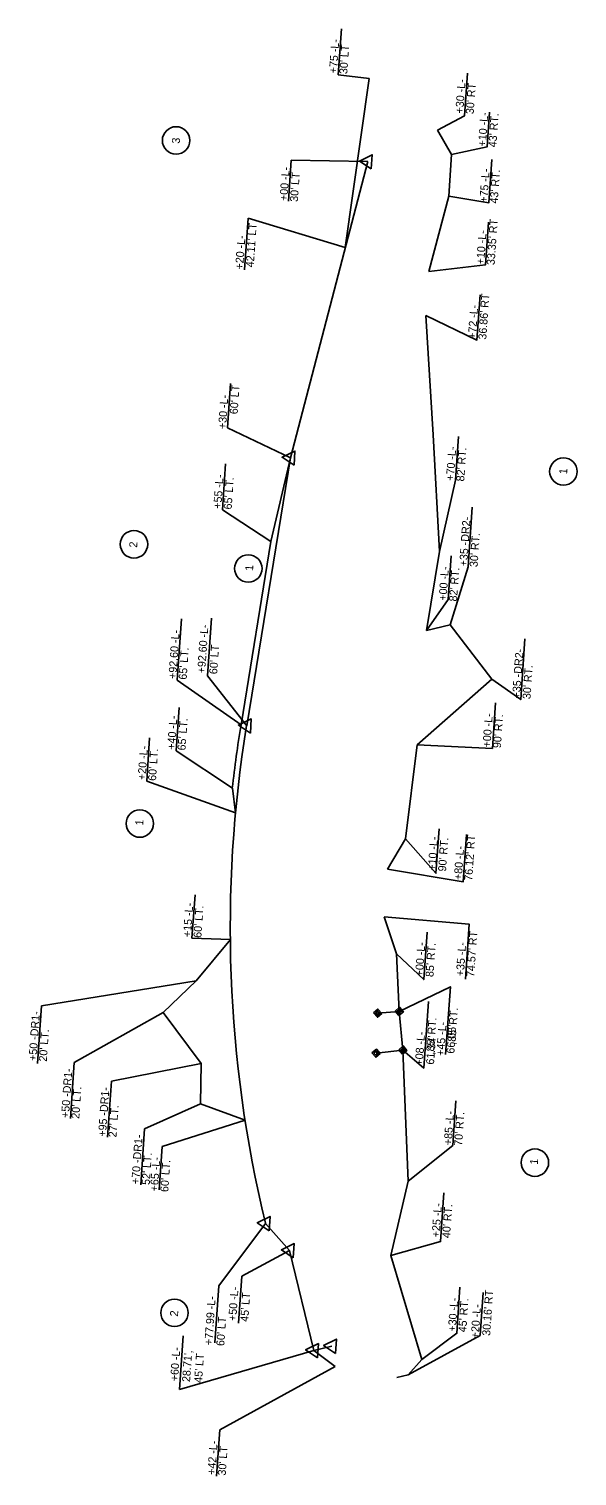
# Model space of a CAD drawing. Extents: x 2599205 to 2599684, y 728753 to 730019.
import ezdxf

# ---------------------------------------------------------------- set-up
doc = ezdxf.new("R2010")
doc.units = 0
for name, color, linetype in [('Default', 7, 'Continuous'), ('Prop Easement Construction', 7, 'Continuous'), ('Prop Easement Construction Station Offsets', 7, 'Continuous'), ('Prop Easement Permanent Drainage', 7, 'Continuous'), ('Prop Easement Permanent Drainage Station Offsets', 7, 'Continuous'), ('Prop Parcel Number CELL', 7, 'Continuous'), ('Prop ROW Marker CELL', 7, 'Continuous'), ('Prop ROW Permanent Easement CELL', 7, 'Continuous'), ('Prop ROW RW Lines', 7, 'Continuous'), ('Prop ROW Station Offsets', 7, 'Continuous')]:
    doc.layers.add(name, color=color, linetype=linetype)

msp = doc.modelspace()

# ---------------------------------------------------------------- linework, layer by layer
at = {"layer": 'Default'}
msp.add_line((2599526.3, 728839.4), (2599536.2, 728841.8), dxfattribs=at)
at = {"layer": 'Prop Easement Construction'}
for p, q in [((2599481.2, 729827.7), (2599502.2, 729975.7)), ((2599574.3, 729909.3), (2599562.1, 729930.5)), ((2599571.9, 729872.8), (2599574.3, 729909.3)), ((2599554.4, 729806.8), (2599571.9, 729872.8)), ((2599558.2, 729664), (2599551.8, 729768.4)), ((2599563.8, 729561.8), (2599558.2, 729664)), ((2599416.3, 729570.6), (2599433.3, 729643.9)), ((2599390.2, 729410.4), (2599416.3, 729570.6)), ((2599552.5, 729492.7), (2599563.8, 729561.8)), ((2599552.5, 729492.7), (2599573, 729497.9)), ((2599609.5, 729450.3), (2599573, 729497.9)), ((2599544.3, 729392.7), (2599609.5, 729450.3)), ((2599534, 729310.5), (2599544.3, 729392.7)), ((2599385.4, 729333.4), (2599382.6, 729355)), ((2599518.2, 729283.9), (2599534, 729310.5)), ((2599526, 729210), (2599515.4, 729242.3)), ((2599350.8, 729186.3), (2599380.8, 729222.5)), ((2599528.5, 729159.6), (2599526, 729210)), ((2599322.1, 729158.5), (2599350.8, 729186.3)), ((2599355.3, 729114.1), (2599322.1, 729158.5)), ((2599536.3, 729011.1), (2599531.7, 729125.8)), ((2599354.7, 729078.8), (2599355.3, 729114.1)), ((2599393.6, 729064.5), (2599354.7, 729078.8)), ((2599521.1, 728946.2), (2599536.3, 729011.1)), ((2599548.3, 728855), (2599521.1, 728946.2)), ((2599472.6, 728849.1), (2599453.8, 728863.1)), ((2599536.2, 728841.8), (2599548.3, 728855))]:
    msp.add_line(p, q, dxfattribs=at)
msp.add_arc((2600480.7, 729232.5), 1105, 170.7363, 173.6343, dxfattribs=at)
at = {"layer": 'Prop Easement Construction Station Offsets'}
for p, q in [((2599475.2, 729978.8), (2599478, 730019)), ((2599502.2, 729975.7), (2599475.2, 729978.8)), ((2599393.3, 729808.4), (2599396.4, 729853.4)), ((2599481.2, 729827.7), (2599396.4, 729853.4)), ((2599373.8, 729598.4), (2599376.5, 729638.6)), ((2599416.3, 729570.6), (2599373.8, 729598.4)), ((2599334.4, 729449.5), (2599338.1, 729503.1)), ((2599390.2, 729410.4), (2599334.4, 729449.5)), ((2599333.4, 729387.6), (2599336, 729425.4)), ((2599307.6, 729361.1), (2599310.2, 729398.9)), ((2599382.6, 729355), (2599333.4, 729387.6)), ((2599385.4, 729333.4), (2599307.6, 729361.1)), ((2599347.2, 729223.7), (2599349.9, 729261.5)), ((2599380.8, 729222.5), (2599347.2, 729223.7)), ((2599350.8, 729186.3), (2599215.5, 729164.5)), ((2599212, 729113.9), (2599215.5, 729164.5)), ((2599322.1, 729158.5), (2599244.3, 729114.9)), ((2599240.9, 729065.9), (2599244.3, 729114.9)), ((2599355.3, 729114.1), (2599276.7, 729098.5)), ((2599273.4, 729049.5), (2599276.7, 729098.5)), ((2599354.7, 729078.8), (2599305.8, 729057)), ((2599393.6, 729064.5), (2599321.2, 729041.4)), ((2599302.4, 729008), (2599305.8, 729057)), ((2599318.6, 729003.6), (2599321.2, 729041.4)), ((2599472.6, 728849.1), (2599371.6, 728793.5)), ((2599368.8, 728753.1), (2599371.6, 728793.5))]:
    msp.add_line(p, q, dxfattribs=at)
for points in [[(2599562.1, 729930.5), (2599585.6, 729942.9), (2599588.2, 729980.4)], [(2599574.3, 729909.3), (2599605.3, 729915.8), (2599607.4, 729946.3)], [(2599571.9, 729872.8), (2599607, 729867), (2599609.6, 729904.7)], [(2599554.4, 729806.8), (2599604.1, 729812.8), (2599606.6, 729850)], [(2599551.8, 729768.4), (2599596.5, 729746.8), (2599599.2, 729786.5)], [(2599563.8, 729561.8), (2599577.8, 729624.4), (2599580.4, 729662.5)], [(2599573, 729497.9), (2599588.8, 729548.6), (2599592.3, 729600.7)], [(2599552.5, 729492.7), (2599571.2, 729520), (2599573.8, 729558.1)], [(2599609.5, 729450.3), (2599634.8, 729432.3), (2599638.5, 729485.5)], [(2599544.3, 729392.7), (2599610, 729389.6), (2599612.7, 729429.5)], [(2599534, 729310.5), (2599560.6, 729280.5), (2599563.3, 729319.3)], [(2599518.2, 729283.9), (2599584.4, 729272.9), (2599587.3, 729314.3)], [(2599515.4, 729242.3), (2599589.8, 729235.8), (2599586.4, 729187.9)], [(2599526, 729210), (2599550, 729187.4), (2599552.9, 729228.9)], [(2599536.3, 729011.1), (2599575.4, 729042.4), (2599578.1, 729081.5)], [(2599521.1, 728946.2), (2599564.7, 728958.2), (2599567.6, 729000.8)], [(2599536.2, 728841.8), (2599599.3, 728876.2), (2599601.9, 728913.7)], [(2599548.3, 728855), (2599578.9, 728878.1), (2599581.6, 728918.5)]]:
    msp.add_lwpolyline(points, dxfattribs=at)
at = {"layer": 'Prop Easement Permanent Drainage'}
for p, q in [((2599528.5, 729159.6), (2599509.6, 729158.1)), ((2599531.7, 729125.8), (2599528.5, 729159.6)), ((2599508.2, 729123.1), (2599531.7, 729125.8))]:
    msp.add_line(p, q, dxfattribs=at)
at = {"layer": 'Prop Easement Permanent Drainage Station Offsets'}
for points in [[(2599528.5, 729159.6), (2599573.3, 729181.2), (2599569.1, 729121.9)], [(2599531.7, 729125.8), (2599550, 729110), (2599554, 729168.2)]]:
    msp.add_lwpolyline(points, dxfattribs=at)
at = {"layer": 'Prop Parcel Number CELL'}
for p, q in [((2599333.3, 729921.5), (2599333.3, 729921.5)), ((2599672.1, 729631.9), (2599672.1, 729631.9)), ((2599296.5, 729568.2), (2599296.5, 729568.2)), ((2599396.5, 729547), (2599396.5, 729547)), ((2599301.6, 729323.9), (2599301.6, 729323.9)), ((2599647.2, 729027.3), (2599647.2, 729027.3)), ((2599331.9, 728895.9), (2599331.9, 728895.9))]:
    msp.add_line(p, q, dxfattribs=at)
for centre in [(2599333.3, 729921.5), (2599672.1, 729631.9), (2599296.5, 729568.2), (2599396.5, 729547), (2599301.6, 729323.9), (2599647.2, 729027.3), (2599331.9, 728895.9)]:
    msp.add_circle(centre, 12, dxfattribs=at)
at = {"layer": 'Prop ROW Marker CELL'}
for p, q in [((2599500.9, 729903), (2599500.9, 729903)), ((2599433.3, 729643.9), (2599433.3, 729643.9)), ((2599395.1, 729409.5), (2599395.1, 729409.5)), ((2599509.6, 729158.1), (2599509.6, 729158.1)), ((2599528.5, 729159.6), (2599528.5, 729159.6)), ((2599508.2, 729123.1), (2599508.2, 729123.1)), ((2599531.7, 729125.8), (2599531.7, 729125.8)), ((2599411.5, 728974.2), (2599411.5, 728974.2)), ((2599432.6, 728950.5), (2599432.6, 728950.5)), ((2599453.8, 728863.1), (2599453.8, 728863.1)), ((2599469.6, 728866.9), (2599469.6, 728866.9))]:
    msp.add_line(p, q, dxfattribs=at)
for points in [[(2599504, 729896.6), (2599493.7, 729903.5), (2599504.9, 729909)], [(2599436.5, 729637.4), (2599426.1, 729644.3), (2599437.3, 729649.8)], [(2599398.3, 729403.1), (2599387.9, 729410), (2599399.1, 729415.5)], [(2599414.6, 728967.7), (2599404.3, 728974.7), (2599415.5, 728980.2)], [(2599435.8, 728944.1), (2599425.5, 728951), (2599436.7, 728956.5)], [(2599456.9, 728856.6), (2599446.6, 728863.5), (2599457.8, 728869)], [(2599472.8, 728860.4), (2599462.4, 728867.4), (2599473.6, 728872.9)]]:
    msp.add_lwpolyline(points, close=True, dxfattribs=at)
at = {"layer": 'Prop ROW Permanent Easement CELL'}
for points in [[(2599506, 729158.4), (2599509.9, 729161.7), (2599513.2, 729157.9), (2599509.4, 729154.5)], [(2599507.8, 729158.3), (2599509.8, 729159.9), (2599511.4, 729158), (2599509.5, 729156.3)], [(2599524.9, 729159.8), (2599528.8, 729163.2), (2599532.1, 729159.3), (2599528.3, 729156)], [(2599526.7, 729159.7), (2599528.7, 729161.4), (2599530.3, 729159.5), (2599528.4, 729157.8)], [(2599528.1, 729126), (2599532, 729129.4), (2599535.3, 729125.5), (2599531.5, 729122.2)], [(2599529.9, 729125.9), (2599531.8, 729127.6), (2599533.5, 729125.6), (2599531.6, 729124)], [(2599504.6, 729123.4), (2599508.5, 729126.7), (2599511.8, 729122.9), (2599508, 729119.5)], [(2599506.4, 729123.2), (2599508.3, 729124.9), (2599510, 729123), (2599508.1, 729121.3)]]:
    msp.add_lwpolyline(points, close=True, dxfattribs=at)
at = {"layer": 'Prop ROW RW Lines'}
for p, q in [((2599433.3, 729643.9), (2599500.9, 729903)), ((2599395.1, 729409.5), (2599433.3, 729643.9)), ((2599432.6, 728950.5), (2599411.5, 728974.2)), ((2599453.8, 728863.1), (2599432.6, 728950.5)), ((2599469.6, 728866.9), (2599453.8, 728863.1))]:
    msp.add_line(p, q, dxfattribs=at)
msp.add_arc((2600480.7, 729232.5), 1100, 170.7363, 193.5781, dxfattribs=at)
at = {"layer": 'Prop ROW Station Offsets'}
for p, q in [((2599434.1, 729904.3), (2599431.6, 729868.4)), ((2599500.9, 729903), (2599434.1, 729904.3)), ((2599380.9, 729708.8), (2599378.2, 729670.2)), ((2599433.3, 729643.9), (2599378.2, 729670.2)), ((2599364.3, 729503.6), (2599360.8, 729453.1)), ((2599395.1, 729409.5), (2599360.8, 729453.1)), ((2599411.5, 728974.2), (2599370.6, 728919.4)), ((2599432.6, 728950.5), (2599390.7, 728928.1)), ((2599387.8, 728887), (2599390.7, 728928.1)), ((2599370.6, 728919.4), (2599367.1, 728869.6)), ((2599336.3, 728828.9), (2599339.6, 728875.9)), ((2599453.8, 728863.1), (2599336.3, 728828.9))]:
    msp.add_line(p, q, dxfattribs=at)

# ---------------------------------------------------------------- texts
at = {"layer": 'Prop Easement Construction Station Offsets'}
for s, p in [('+75 -L-', (2599474, 729980)), ("30' LT", (2599483, 729979.3)), ('+30 -L-', (2599584.5, 729944.9)), ("30' RT", (2599593.6, 729944.3)), ('+10 -L-', (2599604.3, 729916)), ("43' RT.", (2599613.4, 729915.3)), ('+75 -L-', (2599605.6, 729866.8)), ("43' RT.", (2599614.6, 729866.1)), (" 42.11' LT", (2599401, 729807.7)), ("33.35' RT", (2599611.9, 729812.3)), ('+20 -L-', (2599391.9, 729808.4)), ('+10 -L-', (2599602.8, 729812.9)), ("36.86' RT", (2599604.6, 729747.1)), ('+72 -L-', (2599595.5, 729747.7)), ('+70 -L-', (2599576.3, 729623.6)), ("82' RT.", (2599585.3, 729623)), ('+55 -L-', (2599372.8, 729599.1)), ("65' LT.", (2599381.9, 729598.5)), ('+35 -DR2-', (2599587.9, 729548.7)), ("30' RT.", (2599597, 729548.1)), ('+00 -L-', (2599569.9, 729518.7)), ("82' RT.", (2599579, 729518)), ('+92.60 -L-', (2599333.5, 729450.2)), ("65' LT.", (2599342.5, 729449.6)), ('+35 -DR2-', (2599634.2, 729433.2)), ("30' RT.", (2599643.3, 729432.6)), ('+00 -L-', (2599608.3, 729390.3)), ("90' RT.", (2599617.4, 729389.7)), ('+40 -L-', (2599332.4, 729388.3)), ("65' LT.", (2599341.5, 729387.7)), ('+20 -L-', (2599306.6, 729361.8)), ("60' LT.", (2599315.7, 729361.1)), ('+10 -L-', (2599560.4, 729282.5)), ("90' RT.", (2599569.4, 729281.8)), ("76.12' RT", (2599592.3, 729273.7)), ('+80 -L-', (2599583.2, 729274.3)), ('+15 -L-', (2599346.3, 729224.4)), ("60' LT.", (2599355.4, 729223.8)), ("74.57' RT", (2599594.1, 729189.5)), ('+00 -L-', (2599549.3, 729190.1)), ("85' RT.", (2599558.4, 729189.5)), ('+35 -L-', (2599585, 729190.2)), ('+50 -DR1-', (2599211.2, 729116.1)), ("20' LT.", (2599220.2, 729115.5)), ('+50 -DR1-', (2599239.6, 729066.2)), ("20' LT.", (2599248.6, 729065.5)), ('+95 -DR1-', (2599272, 729049.8)), ("27' LT.", (2599281.1, 729049.2)), ('+85 -L-', (2599574.4, 729042.4)), ("70' RT.", (2599583.5, 729041.8)), ('+70 -DR1-', (2599301.1, 729008.3)), ("52' LT.", (2599310.2, 729007.6)), ('+65 -L-', (2599317.4, 729002)), ("60' LT.", (2599326.4, 729001.4)), ('+25 -L-', (2599563.8, 728961.8)), ("40' RT.", (2599572.9, 728961.1)), ("30.16' RT", (2599608, 728875.6)), ('+30 -L-', (2599578, 728879.3)), ("45' RT.", (2599587.1, 728878.7)), ('+20 -L-', (2599598, 728873.4)), ('+42 -L-', (2599367.6, 728754)), ("30' LT", (2599376.7, 728753.4))]:
    msp.add_text(s, height=7, rotation=86.0422, dxfattribs=at).set_placement(p)
at = {"layer": 'Prop Easement Permanent Drainage Station Offsets'}
for s, p in [("    ,85' RT.", (2599558.2, 729111.4)), ("    ,85' RT.", (2599576.9, 729119.9)), ('+08 -L-', (2599549.1, 729112)), ('+45 -L-', (2599567.8, 729120.5)), ("66.05'", (2599576.7, 729122.5)), ("61.34'", (2599558.9, 729112.9))]:
    msp.add_text(s, height=7, rotation=86.0422, dxfattribs=at).set_placement(p)
at = {"layer": 'Prop ROW Station Offsets'}
for s, rotation, p in [('3', 86.0422, (2599336.5, 729918.5)), ('+00 -L-', 86.0601, (2599430.7, 729868.3)), ("30' LT", 86.0601, (2599439.8, 729867.6)), ('+30 -L-', 86.0601, (2599377, 729668.8)), ("60' LT", 86.0601, (2599387.1, 729681.8)), ('1', 86.0422, (2599675.3, 729629.3)), ('2', 86.0422, (2599299.2, 729565.1)), ('1', 86.0422, (2599400.6, 729544.8)), ('+92.60 -L-', 86.0601, (2599358.7, 729455.1)), ("60' LT", 86.0601, (2599369.2, 729454.4)), ('1', 86.0422, (2599304.5, 729322.1)), ('1', 86.0422, (2599649.7, 729025.4)), ('+50 -L-', 86.0422, (2599385.9, 728888.6)), ("45' LT", 86.0422, (2599396.4, 728887.9)), ('+77.99 -L-', 86.0422, (2599365, 728867.4)), ('2', 86.0422, (2599334.9, 728892.5)), ("60' LT", 86.0422, (2599375.4, 728866.7)), ('+60 -L-', 86.0422, (2599335, 728835.9)), ("28.71',", 86.0422, (2599345.5, 728835.2)), ("45' LT", 86.0422, (2599356, 728834.5))]:
    msp.add_text(s, height=7, rotation=rotation, dxfattribs=at).set_placement(p)

doc.saveas('drawing.dxf')
